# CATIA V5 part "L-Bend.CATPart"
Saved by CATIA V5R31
Part number: L-Bend
Bounding box of the stored display mesh (mm): x -50 to 50, y -130 to 15, z -50 to 100
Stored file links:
  D:\PROJECTS\Project 2021\US EDITION\CATIA V5 6R 2021\Resources\Part Files\c12_catia_v5_6r2021_prt\c12_catia_v5-6r2021 figr_12-39\L-Bend.CATPart
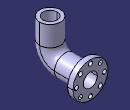
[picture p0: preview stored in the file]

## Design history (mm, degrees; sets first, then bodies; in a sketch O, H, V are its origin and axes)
Body1 (main body)
  Sketch1 on yz-plane, origin (0, 0, 0), H (0, 1, 0), V (0, 0, 1)
    line L1 (0, 0) -> (-57.4642, 0)
    point P1 (-100, 0)
    line L2 (-100, 42.5358) -> (-100, 100)
    point P2 (-100, 100)
    arc A1 centre (-57.4642, 42.5358) radius 42.5358 from (-100, 42.5358) to (-57.4642, 0) ccw
    distance P1 P2 = 100
    distance O P1 = 100
    radius A1 = 42.5358
    horizontal: L1 H
    vertical: L2 V
    coincidence: L2 P1, L1 P1
    tangency: A1 L2, A1 L1
  Sketch2 on zx-plane, origin (0, 0, 0), H (-1, 0, 0), V (0, 0, 1)
    circle A1 centre (0, 0) radius 30
    point P1 (0, -30)
    radius A1 = 30
    coincidence: A1 P1, P1 V
  Rib1: profile Sketch2, centre curve Sketch1
  Shell1: ExtOffset 0, Face (face of Rib1; face of Rib1), IntOffset 10
  Sketch3 on face of Rib1, origin (0, 0, 0), H (-1, 0, 0), V (0, 0, 1)
    circle A1 centre (0, 0) radius 50
    point P1 (0, -50)
    projected circle E1 centre (0, 0) radius 20 from edge [face of Shell1 | face of Rib1]
    radius A1 = 50
    coincidence: A1 P1, P1 V
  Pad1: profile Sketch3, direction (0, 1, 0), length 15
  Sketch4 on face of Pad1, origin (0, 15, 0), H (-1, 0, 0), V (0, 0, 1)
    circle A1 centre (0, -40) radius 6
    point P1 (0, -40)
    radius A1 = 6
    distance H P1 = 40
    coincidence: P1 V
  Pocket1: profile Sketch4, direction (0, -1, 0), length 15
  CircPattern1: of Pocket1, instances 8, angular step 45, axis from face of Pad1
